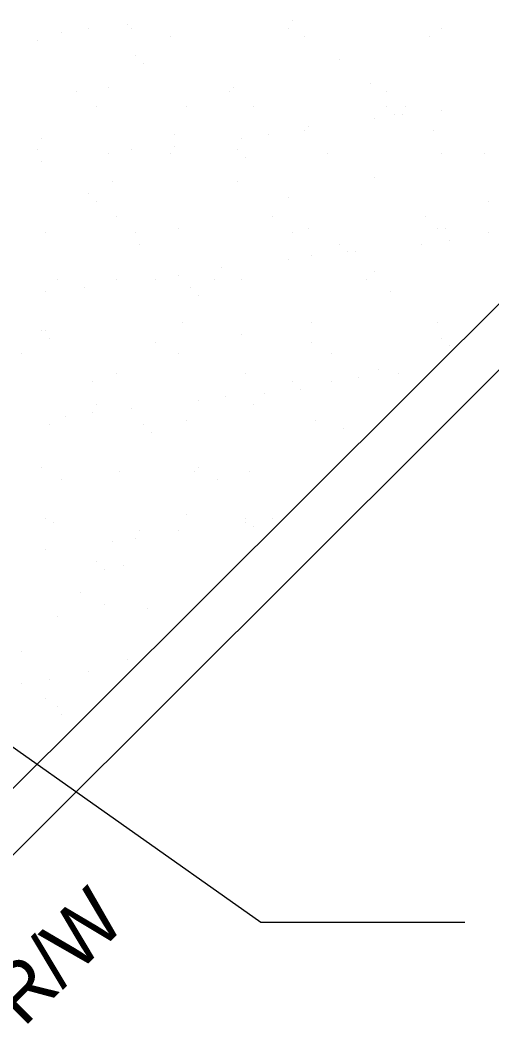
# Model space of a CAD drawing. Extents: x -118779 to -116979, y -104389 to -102939.
# Drawn here: x -118513.7 to -118463.7, y -103205 to -103098.8 of the extents above; entities that cross this region are included whole.
import ezdxf

# ---------------------------------------------------------------- set-up
doc = ezdxf.new("R2010")
doc.units = 0
doc.layers.add('G-MARK', color=7, linetype='Continuous')
doc.layers.add('Misc CnstDet(22)', color=7, linetype='Continuous')

msp = doc.modelspace()

# ---------------------------------------------------------------- linework, layer by layer
at = {"layer": 'G-MARK'}
msp.add_lwpolyline([(-118576.94, -103131.61), (-118488.18, -103194.24), (-118466.61, -103194.24)], dxfattribs=at)
at = {"layer": 'Misc CnstDet(22)'}
for p, q in [((-118484.86, -103098.85), (-118484.86, -103098.85)), ((-118509.33, -103100.09), (-118509.33, -103100.09)), ((-118506.43, -103099.68), (-118506.43, -103099.68)), ((-118502.28, -103099.26), (-118502.28, -103099.26)), ((-118501.86, -103099.68), (-118501.86, -103099.68)), ((-118485.27, -103099.68), (-118485.27, -103099.68)), ((-118469.1, -103099.68), (-118469.1, -103099.68)), ((-118511.82, -103100.92), (-118511.82, -103100.92)), ((-118497.72, -103100.51), (-118497.72, -103100.51)), ((-118483.61, -103100.51), (-118483.61, -103100.51)), ((-118470.34, -103100.51), (-118470.34, -103100.51)), ((-118501.45, -103102.58), (-118501.45, -103102.58)), ((-118500.62, -103103.41), (-118500.62, -103103.41)), ((-118479.88, -103102.99), (-118479.88, -103102.99)), ((-118476.56, -103105.48), (-118476.56, -103105.48)), ((-118507.67, -103106.31), (-118507.67, -103106.31)), ((-118504.35, -103105.9), (-118504.35, -103105.9)), ((-118491.49, -103106.31), (-118491.49, -103106.31)), ((-118491.08, -103105.9), (-118491.08, -103105.9)), ((-118474.9, -103106.31), (-118474.9, -103106.31)), ((-118505.6, -103107.97), (-118505.6, -103107.97)), ((-118496.06, -103107.97), (-118496.06, -103107.97)), ((-118489.01, -103107.97), (-118489.01, -103107.97)), ((-118474.9, -103107.97), (-118474.9, -103107.97)), ((-118474.07, -103108.8), (-118474.07, -103108.8)), ((-118473.24, -103108.8), (-118473.24, -103108.8)), ((-118472.83, -103107.97), (-118472.83, -103107.97)), ((-118469.1, -103108.39), (-118469.1, -103108.39)), ((-118476.15, -103109.22), (-118476.15, -103109.22)), ((-118497.3, -103110.88), (-118497.3, -103110.88)), ((-118487.35, -103110.88), (-118487.35, -103110.88)), ((-118483.61, -103110.46), (-118483.61, -103110.46)), ((-118483.2, -103110.05), (-118483.2, -103110.05)), ((-118469.93, -103110.46), (-118469.93, -103110.46)), ((-118511.4, -103111.29), (-118511.4, -103111.29)), ((-118490.25, -103111.29), (-118490.25, -103111.29)), ((-118511.82, -103112.53), (-118511.82, -103112.53)), ((-118504.35, -103112.95), (-118504.35, -103112.95)), ((-118501.86, -103112.53), (-118501.86, -103112.53)), ((-118497.72, -103112.95), (-118497.72, -103112.95)), ((-118497.3, -103112.12), (-118497.3, -103112.12)), ((-118490.66, -103112.53), (-118490.66, -103112.53)), ((-118481.13, -103112.95), (-118481.13, -103112.95)), ((-118469.1, -103112.95), (-118469.1, -103112.95)), ((-118464.53, -103112.95), (-118464.53, -103112.95)), ((-118511.4, -103113.78), (-118511.4, -103113.78)), ((-118489.84, -103113.36), (-118489.84, -103113.36)), ((-118503.94, -103115.85), (-118503.94, -103115.85)), ((-118490.66, -103115.85), (-118490.66, -103115.85)), ((-118476.15, -103115.44), (-118476.15, -103115.44)), ((-118506.43, -103117.1), (-118506.43, -103117.1)), ((-118505.6, -103117.93), (-118505.6, -103117.93)), ((-118485.27, -103117.51), (-118485.27, -103117.51)), ((-118464.12, -103117.93), (-118464.12, -103117.93)), ((-118503.52, -103119.59), (-118503.52, -103119.59)), ((-118486.93, -103119.59), (-118486.93, -103119.59)), ((-118470.76, -103119.59), (-118470.76, -103119.59)), ((-118510.99, -103121.24), (-118510.99, -103121.24)), ((-118501.45, -103121.24), (-118501.45, -103121.24)), ((-118496.89, -103120.83), (-118496.89, -103120.83)), ((-118484.86, -103121.24), (-118484.86, -103121.24)), ((-118483.2, -103120.83), (-118483.2, -103120.83)), ((-118469.51, -103120.83), (-118469.51, -103120.83)), ((-118468.68, -103120.83), (-118468.68, -103120.83)), ((-118464.12, -103121.24), (-118464.12, -103121.24)), ((-118501.03, -103122.49), (-118501.03, -103122.49)), ((-118479.88, -103122.49), (-118479.88, -103122.49)), ((-118471.17, -103122.49), (-118471.17, -103122.49)), ((-118468.27, -103122.07), (-118468.27, -103122.07)), ((-118479.05, -103123.32), (-118479.05, -103123.32)), ((-118478.22, -103123.32), (-118478.22, -103123.32)), ((-118586.48, -103251.89), (-118457.9, -103123.73)), ((-118485.27, -103124.15), (-118485.27, -103124.15)), ((-118482.78, -103123.73), (-118482.78, -103123.73)), ((-118496.89, -103125.81), (-118496.89, -103125.81)), ((-118492.32, -103124.98), (-118492.32, -103124.98)), ((-118476.15, -103125.39), (-118476.15, -103125.39)), ((-118509.74, -103126.22), (-118509.74, -103126.22)), ((-118503.52, -103126.22), (-118503.52, -103126.22)), ((-118499.37, -103126.22), (-118499.37, -103126.22)), ((-118493.15, -103126.22), (-118493.15, -103126.22)), ((-118490.25, -103126.22), (-118490.25, -103126.22)), ((-118476.98, -103126.22), (-118476.98, -103126.22)), ((-118510.99, -103127.47), (-118510.99, -103127.47)), ((-118506.84, -103127.05), (-118506.84, -103127.05)), ((-118495.64, -103127.05), (-118495.64, -103127.05)), ((-118494.81, -103127.88), (-118494.81, -103127.88)), ((-118474.49, -103127.47), (-118474.49, -103127.47)), ((-118496.47, -103130.78), (-118496.47, -103130.78)), ((-118482.78, -103130.78), (-118482.78, -103130.78)), ((-118469.51, -103130.78), (-118469.51, -103130.78)), ((-118511.4, -103131.61), (-118511.4, -103131.61)), ((-118510.99, -103131.61), (-118510.99, -103131.61)), ((-118490.25, -103132.03), (-118490.25, -103132.03)), ((-118510.57, -103132.44), (-118510.57, -103132.44)), ((-118499.37, -103132.86), (-118499.37, -103132.86)), ((-118482.78, -103132.86), (-118482.78, -103132.86)), ((-118469.1, -103132.44), (-118469.1, -103132.44)), ((-118513.48, -103134.1), (-118513.48, -103134.1)), ((-118496.89, -103134.1), (-118496.89, -103134.1)), ((-118480.71, -103134.1), (-118480.71, -103134.1)), ((-118468.27, -103133.27), (-118468.27, -103133.27)), ((-118503.52, -103136.18), (-118503.52, -103136.18)), ((-118489.84, -103136.18), (-118489.84, -103136.18)), ((-118475.73, -103135.76), (-118475.73, -103135.76)), ((-118473.66, -103136.18), (-118473.66, -103136.18)), ((-118506.01, -103137.01), (-118506.01, -103137.01)), ((-118484.86, -103137.01), (-118484.86, -103137.01)), ((-118480.71, -103137.01), (-118480.71, -103137.01)), ((-118477.81, -103136.59), (-118477.81, -103136.59)), ((-118487.76, -103138.25), (-118487.76, -103138.25)), ((-118484.03, -103137.83), (-118484.03, -103137.83)), ((-118505.6, -103139.49), (-118505.6, -103139.49)), ((-118494.81, -103139.08), (-118494.81, -103139.08)), ((-118491.91, -103138.66), (-118491.91, -103138.66)), ((-118489.01, -103139.49), (-118489.01, -103139.49)), ((-118506.01, -103140.32), (-118506.01, -103140.32)), ((-118501.86, -103139.91), (-118501.86, -103139.91)), ((-118510.57, -103141.57), (-118510.57, -103141.57)), ((-118508.91, -103140.74), (-118508.91, -103140.74)), ((-118500.62, -103141.57), (-118500.62, -103141.57)), ((-118496.06, -103141.15), (-118496.06, -103141.15)), ((-118482.37, -103141.15), (-118482.37, -103141.15)), ((-118499.79, -103142.4), (-118499.79, -103142.4)), ((-118479.47, -103141.98), (-118479.47, -103141.98)), ((-118511.4, -103146.13), (-118511.4, -103146.13)), ((-118503.11, -103146.54), (-118503.11, -103146.54)), ((-118495.23, -103146.54), (-118495.23, -103146.54)), ((-118494.81, -103146.13), (-118494.81, -103146.13)), ((-118489.42, -103146.54), (-118489.42, -103146.54)), ((-118509.33, -103147.37), (-118509.33, -103147.37)), ((-118492.74, -103147.37), (-118492.74, -103147.37)), ((-118496.06, -103151.11), (-118496.06, -103151.11)), ((-118510.99, -103151.52), (-118510.99, -103151.52)), ((-118510.16, -103151.94), (-118510.16, -103151.94)), ((-118489.84, -103151.52), (-118489.84, -103151.52)), ((-118489.84, -103151.94), (-118489.84, -103151.94)), ((-118489.01, -103152.35), (-118489.01, -103152.35)), ((-118486.93, -103151.52), (-118486.93, -103151.52)), ((-118501.03, -103152.77), (-118501.03, -103152.77)), ((-118496.89, -103152.77), (-118496.89, -103152.77)), ((-118503.94, -103154.01), (-118503.94, -103154.01)), ((-118501.45, -103153.6), (-118501.45, -103153.6)), ((-118510.99, -103154.84), (-118510.99, -103154.84)), ((-118505.6, -103156.08), (-118505.6, -103156.08)), ((-118502.69, -103156.5), (-118502.69, -103156.5)), ((-118504.77, -103156.91), (-118504.77, -103156.91)), ((-118507.26, -103159.4), (-118507.26, -103159.4)), ((-118504.77, -103160.65), (-118504.77, -103160.65)), ((-118509.74, -103161.89), (-118509.74, -103161.89)), ((-118500.2, -103161.06), (-118500.2, -103161.06)), ((-118513.48, -103165.62), (-118513.48, -103165.62)), ((-118502.28, -103166.45), (-118502.28, -103166.45)), ((-118506.43, -103167.7), (-118506.43, -103167.7)), ((-118513.48, -103168.94), (-118513.48, -103168.94)), ((-118510.57, -103168.53), (-118510.57, -103168.53)), ((-118510.99, -103170.6), (-118510.99, -103170.6)), ((-118509.74, -103171.43), (-118509.74, -103171.43)), ((-118509.33, -103172.26), (-118509.33, -103172.26))]:
    msp.add_line(p, q, dxfattribs=at)
msp.add_lwpolyline([(-118581.5, -103791.92), (-118581.5, -103253.97), (-118455.82, -103128.71), (-118400.25, -103128.71)], dxfattribs=at)
for radius in [223.87, 209.05, 202.47]:
    msp.add_arc((-118457.89, -103252.04), radius, 90, 180, dxfattribs=at)

# ---------------------------------------------------------------- texts
msp.add_text('R/W', height=6, rotation=45, dxfattribs=at).set_placement((-118513.31, -103205.48))

doc.saveas('drawing.dxf')
